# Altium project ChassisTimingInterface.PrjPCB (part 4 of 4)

## Sheet ChassisTimingInterface_SFP.SchDoc: SFP
size B; Author: M. Pirello; Organization: LIGO Laboratory; Address1: California Institute of Technology; Address2: Massachusetts Institute of Technology; Address3: National Science Foundation; Address4: Australia 2086; DocumentNumber: 3; SheetNumber: 9; SheetTotal: 12; Size: B
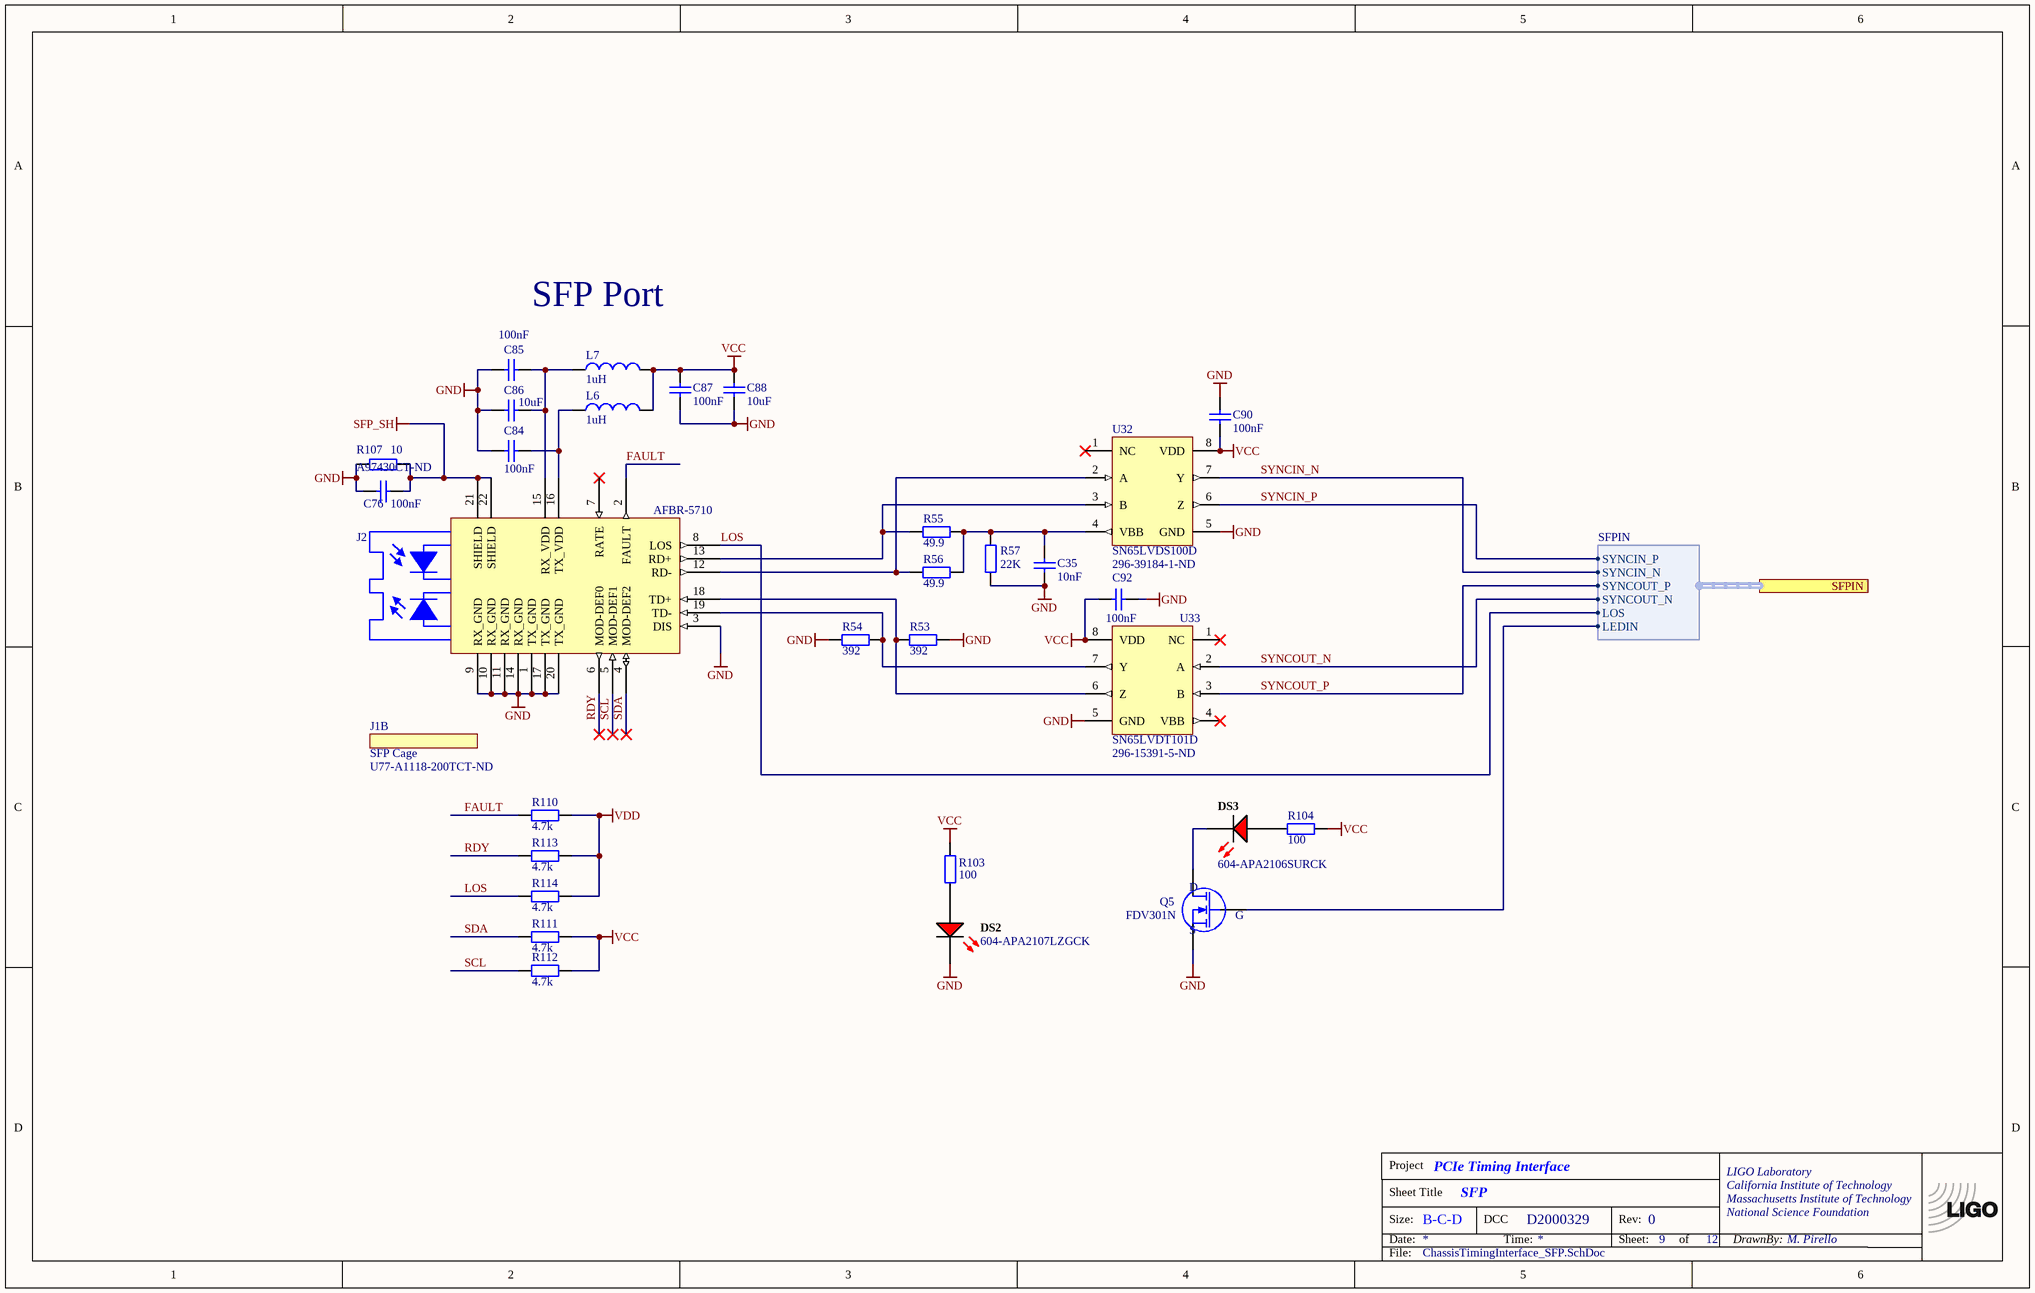
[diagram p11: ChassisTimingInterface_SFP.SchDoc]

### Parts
(Parts that share a designator on the sheet are numbered #1, #2 ... from top to bottom, then left to right.)
*#3  TitleBlock  (value not drawn)  (graphical)
C35  10nF  [CC1005-0402]
C76  100nF  [CC1005-0402]
C84  100nF  [CC1005-0402]
C85  100nF  [CC1005-0402]
C86  10uF  [CC2013-0805]
C87  100nF  [CC1005-0402]
C88  10uF  [CC2013-0805]
C90  100nF  [CC1005-0402]
C92  100nF  [CC1005-0402]
DS2  604-APA2107LZGCK  [KING-LED2107-13-RED-2_V]
DS3  604-APA2106SURCK  [KING-LED2107-13-RED-2_V]
J1B  SFP Cage  Supplier Part Number 1: U77-A1118-200TCT-ND  (mechanical)
J2  AFBR-5710  Supplier Part Number 1: A97430CT-ND  [MSA/SFP2x10]
L6  1uH  [CL2520-1008]
L7  1uH  [CL2520-1008]
Q5  FDV301N  [SO-G3/C2.25]
R53  392  [CR2012-0805]
R54  392  [CR2012-0805]
R55  49.9  [CR1608-0603]
R56  49.9  [CR1608-0603]
R57  22K  [CR2012-0805]
R103  100  [CR1608-0603]
R104  100  [CR1608-0603]
R107  value 10  [CR1005-0402]  (hidden comment: 10.0)
R110  4.7k  [CR1005-0402]
R111  4.7k  [CR1005-0402]
R112  4.7k  [CR1005-0402]
R113  4.7k  [CR1005-0402]
R114  4.7k  [CR1005-0402]
U32  SN65LVDS100D  Supplier Part Number 1: 296-39184-1-ND  [MSOP8]
U33  SN65LVDT101D  Supplier Part Number 1: 296-15391-5-ND  [MSOP8]

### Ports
SFPIN (harness SFPIN)

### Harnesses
SFPIN: SYNCIN_N, SYNCIN_P, SYNCOUT_N, SYNCOUT_P, LEDIN, LOS

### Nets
GND: C35.1 C76.2 C84.1 C85.1 C86.1 C87.1 C88.1 C90.1 C92.1 DS2.1(K) J2.1(TX_GND) J2.3(DIS) J2.9(RX_GND) J2.10(RX_GND) J2.11(RX_GND) J2.14(RX_GND) J2.17(TX_GND) J2.20(TX_GND) Q5.2(S) R53.2 R54.1 R57.2 R107.2 U32.5(GND) U33.5(GND)
SFP_SH: C76.1 J2.21(SHIELD) J2.22(SHIELD) R107.1
VCC: C87.2 C88.2 C90.2 C92.2 L6.2 L7.2 R103.2 R104.2 R111.2 R112.2 U32.8(VDD) U33.8(VDD)
VDD: R110.2 R113.2 R114.2
FAULT: J2.2(FAULT) R110.1
LOS: J2.8(LOS) R114.1 ; port SFPIN.LOS  [project net SFPIN.LOS]
RDY: J2.6(MOD-DEF0) R113.1
SCL: J2.5(MOD-DEF1) R112.1
SDA: J2.4(MOD-DEF2) R111.1
SFPIN.LEDIN: Q5.1(G) ; port SFPIN.LEDIN
SYNCIN_N: U32.7(Y) ; port SFPIN.SYNCIN_N  [project net SFPIN.SYNCIN_N]
SYNCIN_P: U32.6(Z) ; port SFPIN.SYNCIN_P  [project net SFPIN.SYNCIN_P]
SYNCOUT_N: U33.2(A) ; port SFPIN.SYNCOUT_N  [project net SFPIN.SYNCOUT_N]
SYNCOUT_P: U33.3(B) ; port SFPIN.SYNCOUT_P  [project net SFPIN.SYNCOUT_P]
NetC35_2: C35.2 R55.1 R56.1 R57.1 U32.4(VBB)
NetC84_2: C84.2 J2.16(TX_VDD) L6.1
NetC85_2: C85.2 C86.2 J2.15(RX_VDD) L7.1
NetDS2_2: DS2.2(A) R103.1
NetDS3_1: DS3.1(K) Q5.3(D)
NetDS3_2: DS3.2(A) R104.1
NetJ2_12: J2.12(RD-) R56.2 U32.2(A)
NetJ2_13: J2.13(RD+) R55.2 U32.3(B)
NetJ2_18: J2.18(TD+) R53.1 U33.6(Z)
NetJ2_19: J2.19(TD-) R54.2 U33.7(Y)

Not connected (* = marked no-connect by the designer): J2 7(RATE)* 23(POST) 24(POST); U32 1(NC)*; U33 1(NC)* 4(VBB)*

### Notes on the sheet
- SFP Port

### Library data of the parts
C35 = ChipCap: C0402 0.01uF; Part Number: 311-1349-1-ND; Tolerance: 10%
C76 C84 C85 C87 C90 C92 = ChipCap: C0402 0.1uF; Part Number: 1276-6720-1-ND; Tolerance: 10%
C86 C88 = ChipCap: C0805 10uF; Part Number: 1276-6454-1-ND; Tolerance: 10%
DS2 = CMP-0245-00001-1: 2.1x0.7mm Right Angle SMT LED, 1.3mm Thickness, Green
DS3 = CMP-0245-00001-1: 2.1x0.7mm Right Angle SMT LED, 1.3mm Thickness, Red
J1B = Partlist
J2 = AFBR-5710: fiber optic transceiver, 1.25GB/s, MM, LC, SFP
L6 L7 = ChipInductor: Inductor; Part Number: 994-1008LS-102XJLB
Q5 = FDV301N: FDV301N, Digital FET, N-channel, SOT23; Part Number: FDV301NCT-ND
R53 R54 = ChipRes1: R0805 392; Part Number: P20236CT-ND; Tolerance: 0.1%
R55 R56 = ChipRes1: R0603 49.9; Part Number: RR08Q49.9DCT-ND; Tolerance: 0.1%
R57 = ChipRes1: R0805 22k; Part Number: RR12P22.0KDCT-ND; Tolerance: 0.1%
R103 R104 = ChipRes1: R0603 100; Part Number: RR08P100DCT-ND; Tolerance: 0.1%
R107 = ChipRes1: R0402 10; Part Number: A127127CT-ND; Tolerance: 0.1%
R110-R114 = ChipRes1: R0402 4.7k; Part Number: RR05P4.7KDCT-ND; Tolerance: 0.1%
U32 U33 = SN65LVDS100: DIFF TRANSLATOR

## Sheet ChassisTimingInterface7.SchDoc: External Sync
size B; Author: M. Pirello; Organization: LIGO Laboratory; Address1: California Institute of Technology; Address2: Massachusetts Institute of Technology; Address3: National Science Foundation; Address4: Australia 2086; DocumentNumber: 8; SheetNumber: 8; SheetTotal: 12; Size: B
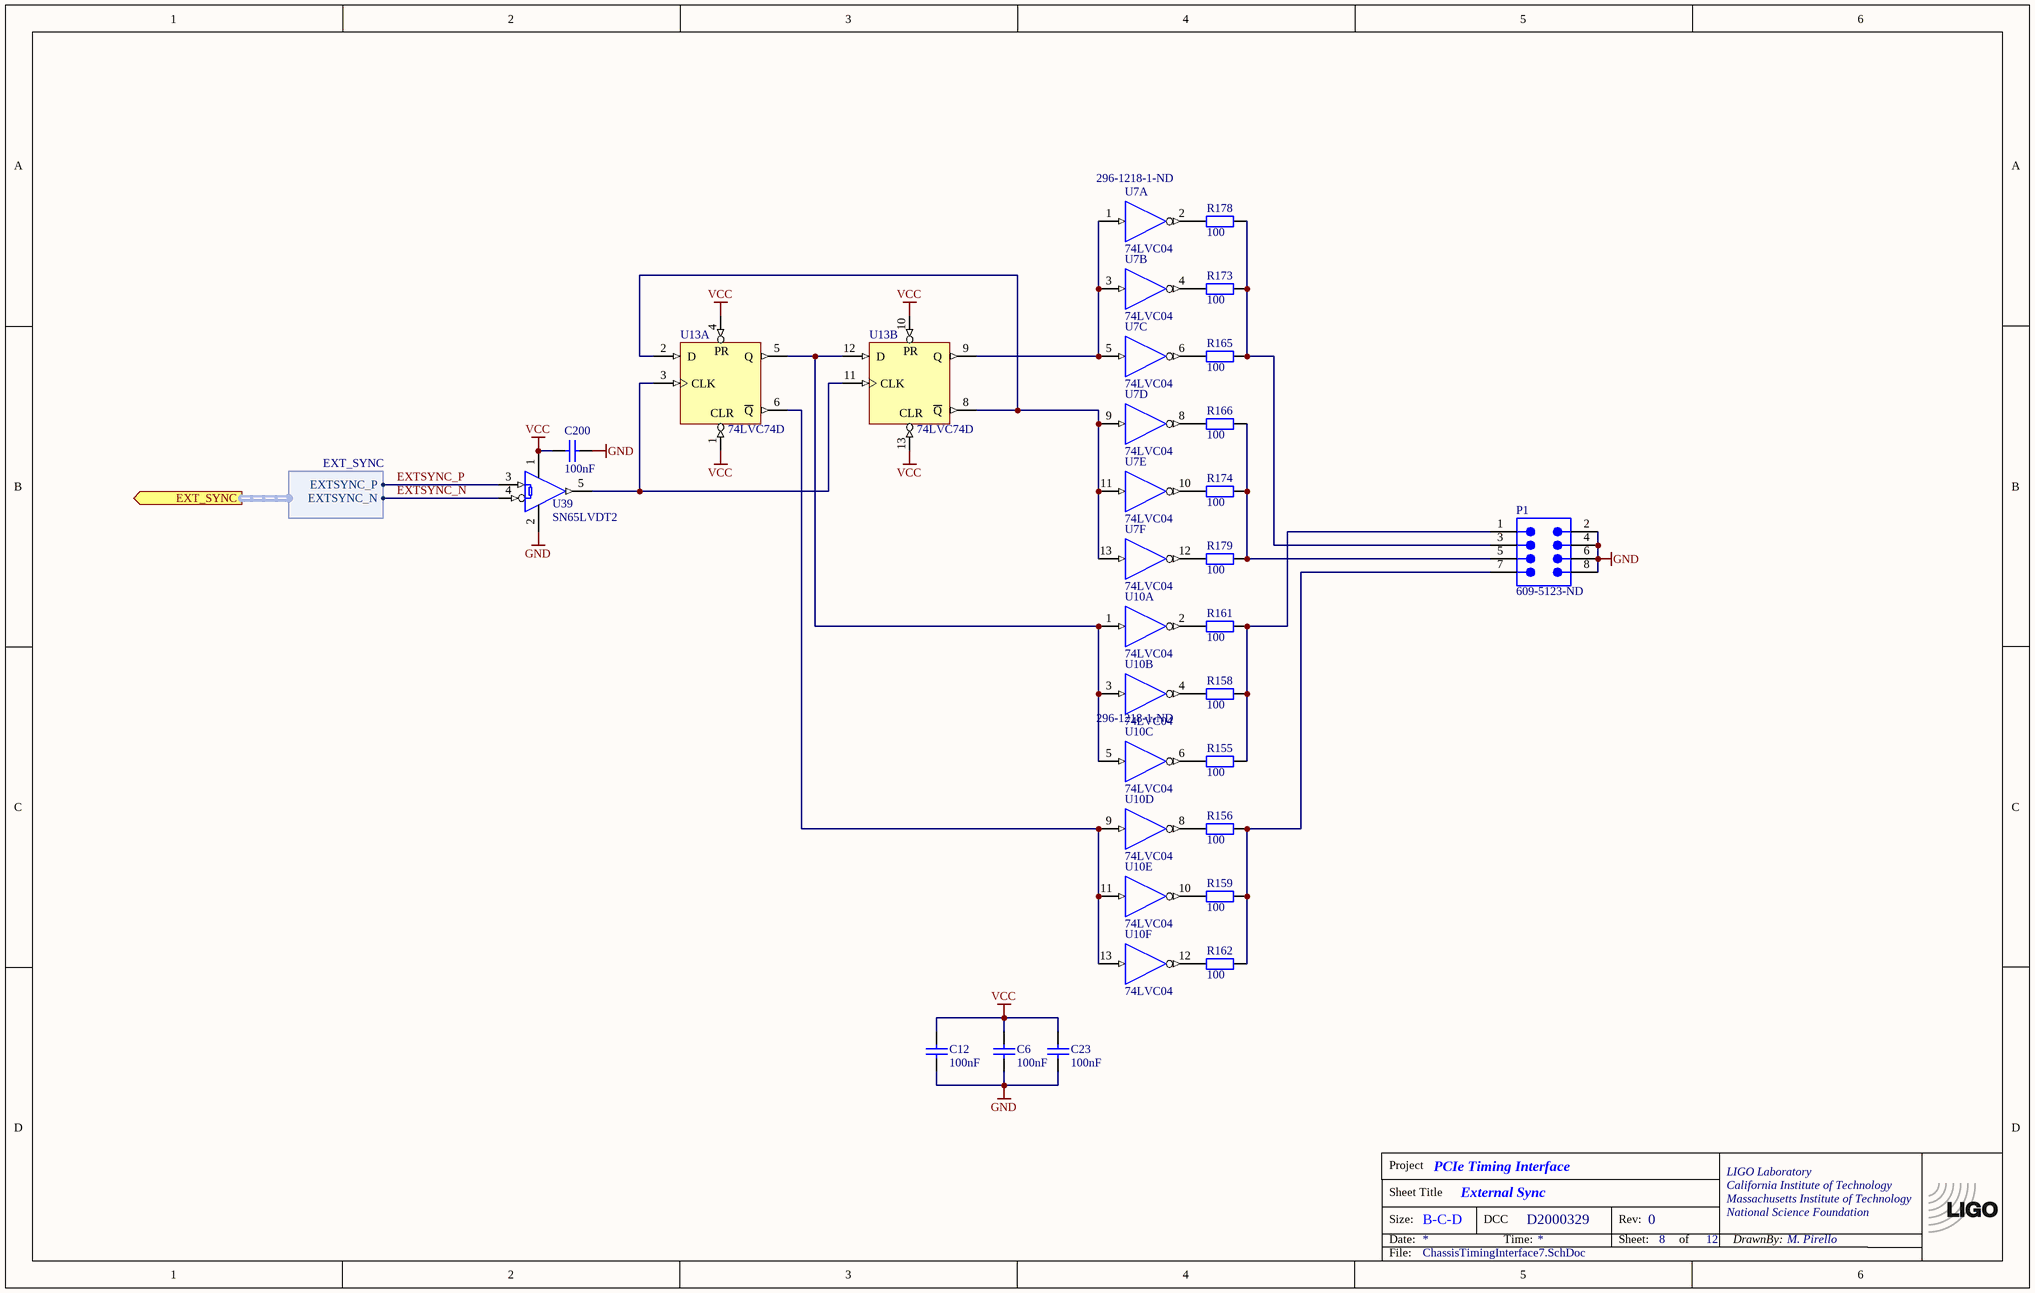
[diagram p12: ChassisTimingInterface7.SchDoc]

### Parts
(Parts that share a designator on the sheet are numbered #1, #2 ... from top to bottom, then left to right.)
*?#8  TitleBlock  (value not drawn)  (graphical)
?#2  (no value)  (no BOM)
C6  100nF  [CC1005-0402]
C12  100nF  [CC1005-0402]
C23  100nF  [CC1005-0402]
C200  100nF  [CC1005-0402]
P1  609-5123-ND  [9181089621]
R155  100  [CR1608-0603]
R156  100  [CR1608-0603]
R158  100  [CR1608-0603]
R159  100  [CR1608-0603]
R161  100  [CR1608-0603]
R162  100  [CR1608-0603]
R165  100  [CR1608-0603]
R166  100  [CR1608-0603]
R173  100  [CR1608-0603]
R174  100  [CR1608-0603]
R178  100  [CR1608-0603]
R179  100  [CR1608-0603]
U7  74LVC04  Supplier Part Number 1: 296-1218-1-ND  [TSSOP14]  (parts A,B,C,D,E,F of 6)
U10  74LVC04  [TSSOP14]  (parts A,B,C,D,E,F of 6)
U13  74LVC74D  [TSSOP14]  (parts A,B of 2)
U39  SN65LVDT2  [SO-G5/E2.4]

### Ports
EXT_SYNC (out, harness EXT_SYNC)

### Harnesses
EXT_SYNC: EXTSYNC_N, EXTSYNC_P

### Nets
GND: C6.2 C12.2 C23.2 C200.1 P1.2 P1.4 P1.6 P1.8 U7.7(GND) U10.7(GND) U13.7(GND) U39.2(GND)
VCC: C6.1 C12.1 C23.1 C200.2 U7.14(VCC) U10.14(VCC) U13.1(CLR) U13.4(PR) U13.10(PR) U13.13(CLR) U13.14(VCC) U39.1(VCC)
EXTSYNC_N: U39.4(B) ; port EXT_SYNC.EXTSYNC_N  [project net EXT_SYNC.EXTSYNC_N]
EXTSYNC_P: U39.3(A) ; port EXT_SYNC.EXTSYNC_P  [project net EXT_SYNC.EXTSYNC_P]
NetP1_1: P1.1 R155.2 R158.2 R161.2
NetP1_3: P1.3 R165.2 R173.2 R178.2
NetP1_5: P1.5 R166.2 R174.2 R179.2
NetP1_7: P1.7 R156.2 R159.2 R162.2
NetR155_1: R155.1 U10.6(Y)
NetR156_1: R156.1 U10.8(Y)
NetR158_1: R158.1 U10.4(Y)
NetR159_1: R159.1 U10.10(Y)
NetR161_1: R161.1 U10.2(Y)
NetR162_1: R162.1 U10.12(Y)
NetR165_1: R165.1 U7.6(Y)
NetR166_1: R166.1 U7.8(Y)
NetR173_1: R173.1 U7.4(Y)
NetR174_1: R174.1 U7.10(Y)
NetR178_1: R178.1 U7.2(Y)
NetR179_1: R179.1 U7.12(Y)
NetU7_1: U7.1(A) U7.3(A) U7.5(A) U13.9(Q)
NetU7_9: U7.9(A) U7.11(A) U7.13(A) U13.2(D) U13.8(~{Q})
NetU10_1: U10.1(A) U10.3(A) U10.5(A) U13.5(Q) U13.12(D)
NetU10_9: U10.9(A) U10.11(A) U10.13(A) U13.6(~{Q})
NetU13_3: U13.3(CLK) U13.11(CLK) U39.5(R)

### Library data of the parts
?#2 = LIGO_logo: LIGO logo
C6 C12 C23 C200 = ChipCap: as C76 on sheet ChassisTimingInterface_SFP
P1 = 09 18 108 9621: Flat Cable Connector (IDC), PCB Transition Connector, 2 Rows, Solder Pin, 8 Contacts
R155 R156 R158 R159 R161 R162 R165 R166 R173 R174 R178 R179 = ChipRes1: as R103 on sheet ChassisTimingInterface_SFP
U7 = SN74AHCT04D: Hex Inverter
U10 = SN74AHCT04D: Hex Inverter; Part Number: 296-1218-1-ND
U13 = 74F74PC: Dual D-Type Positive Edge-Triggered Flip-Flop; Part Number: 296-1240-5-ND
U39 = SN65LVDT2DBV: Single LVDS Receiver with 100 Ohm termination; Part Number: 296-6896-1-ND

## Sheet ChassisTimingInterface_XADC.SchDoc: XADC
size B; DocumentNumber: 5; Revision: C; SheetNumber: 10; SheetTotal: 12
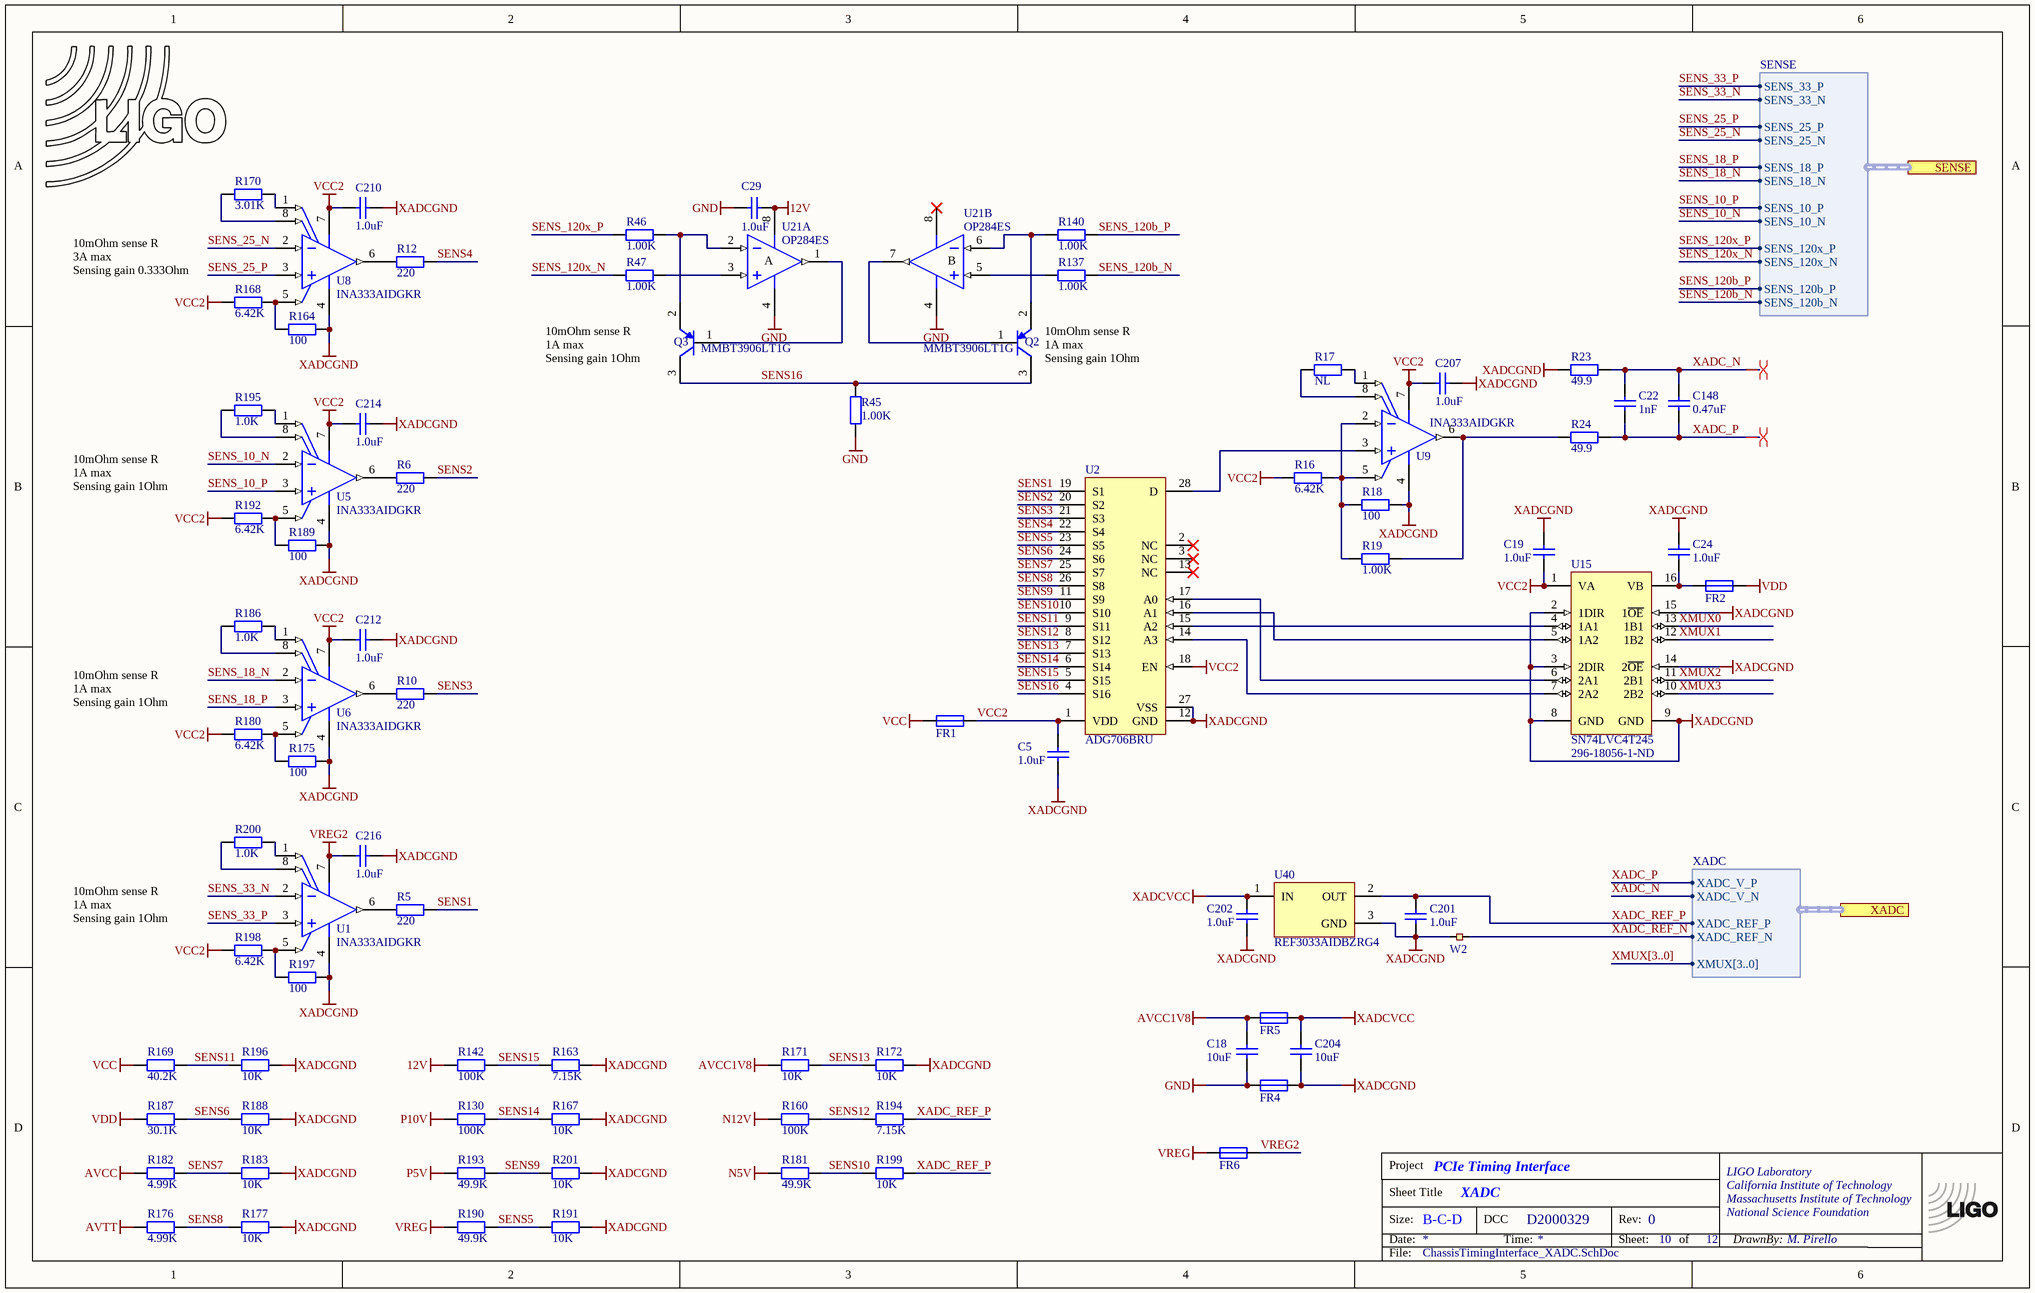
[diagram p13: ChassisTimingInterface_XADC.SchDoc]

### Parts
(Parts that share a designator on the sheet are numbered #1, #2 ... from top to bottom, then left to right.)
*#4  TitleBlock  (value not drawn)  (graphical)
C5  1.0uF  [CC1608-0603]
C18  10uF  [CC2013-0805]
C19  1.0uF  [CC1608-0603]
C22  1nF  [CC1005-0402]
C24  1.0uF  [CC1608-0603]
C29  1.0uF  [CC1608-0603]
C148  0.47uF  [CAPC0603X33X15NL03T05]
C201  1.0uF  [CC1608-0603]
C202  1.0uF  [CC1608-0603]
C204  10uF  [CC2013-0805]
C207  1.0uF  [CC1608-0603]
C210  1.0uF  [CC1608-0603]
C212  1.0uF  [CC1608-0603]
C214  1.0uF  [CC1608-0603]
C216  1.0uF  [CC1608-0603]
FR1  BLM31PG121  [CC3216-1206]  (value not drawn)
FR2  BLM31PG121  [CC3216-1206]  (value not drawn)
FR4  BLM31PG121  [CC3216-1206]  (value not drawn)
FR5  BLM31PG121  [CC3216-1206]  (value not drawn)
FR6  BLM31PG121  [CC3216-1206]  (value not drawn)
LOGO4#2  LIGO logo  [LIGO_LOGO]  (value not drawn)  (graphical)
Q2  MMBT3906LT1G  [ONSC-SOT-23-3-318-08_V]
Q3  MMBT3906LT1G  [ONSC-SOT-23-3-318-08_V]
R5  220  [CR1608-0603]
R6  220  [CR1608-0603]
R10  220  [CR1608-0603]
R12  220  [CR1608-0603]
R16  6.42K  [CR1608-0603]
R17  NL  [CR1608-0603]
R18  100  [CR1608-0603]
R19  value 1.00K  [CR1608-0603]  (hidden comment: 1.0k)
R23  49.9  [CR1608-0603]
R24  49.9  [CR1608-0603]
R45  value 1.00K  [CR1608-0603]  (hidden comment: 1.0k)
R46  value 1.00K  [CR1608-0603]  (hidden comment: 1.0k)
R47#2  value 1.00K  [CR1608-0603]  (hidden comment: 1.0k)
R130  100K  [CR1005-0402]
R137  value 1.00K  [CR1608-0603]  (hidden comment: 1.0k)
R140  value 1.00K  [CR1608-0603]  (hidden comment: 1.0k)
R142  100K  [CR1005-0402]
R160  100K  [CR1005-0402]
R163  7.15K  [CR1005-0402]
R164  100  [CR1608-0603]
R167  10K  [CR1005-0402]
R168  6.42K  [CR1608-0603]
R169  40.2K  [CR1608-0603]
R170  3.01K  [CR1608-0603]
R171  10K  [CR1005-0402]
R172  10K  [CR1005-0402]
R175  100  [CR1608-0603]
R176  4.99K  [CR1608-0603]
R177  10K  [CR1005-0402]
R180  6.42K  [CR1608-0603]
R181  49.9K  [CR1005-0402]
R182  4.99K  [CR1608-0603]
R183  10K  [CR1005-0402]
R186  1.0K  [CR1608-0603]
R187  30.1K  [CR1608-0603]
R188  10K  [CR1005-0402]
R189  100  [CR1608-0603]
R190  49.9K  [CR1005-0402]
R191  10K  [CR1005-0402]
R192  6.42K  [CR1608-0603]
R193  49.9K  [CR1005-0402]
R194  7.15K  [CR1005-0402]
R195  1.0K  [CR1608-0603]
R196  10K  [CR1005-0402]
R197  100  [CR1608-0603]
R198  6.42K  [CR1608-0603]
R199  10K  [CR1005-0402]
R200  1.0K  [CR1608-0603]
R201  10K  [CR1005-0402]
U1  INA333AIDGKR  [DGK0008A_N]
U2  ADG706BRU  [ADI-RU-28_M]
U5  INA333AIDGKR  [DGK0008A_N]
U6  INA333AIDGKR  [DGK0008A_N]
U8  INA333AIDGKR  [DGK0008A_N]
U9  INA333AIDGKR  [DGK0008A_N]
U15  SN74LVC4T245  Supplier Part Number 1: 296-18056-1-ND  [TSSOP16]
U21  OP284ES  [SO-8_N]  (parts A,B of 2)
U40  REF3033AIDBZRG4  [TI-DBZ3_N]
W2  Net tie  [NETTIE1_SMDTOP]  (value not drawn)  (net tie, no BOM)

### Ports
SENSE (harness SENSE), XADC (harness XADC)

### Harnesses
XADC: XADC_REF_P, XADC_V_N, XADC_V_P, XMUX[3..0], XADC_REF_N
SENSE: SENS_33_P, SENS_33_N, SENS_25_P, SENS_25_N, SENS_18_P, SENS_18_N, SENS_10_P, SENS_10_N, SENS_120x_P, SENS_120x_N, SENS_120b_P, SENS_120b_N

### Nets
12V: C29.1 R47#2.2 R137.1 R142.1 U21.8(V+) ; port SENSE.SENS_120x_N, port SENSE.SENS_120b_N  [also labelled SENS_120b_N, SENS_120x_N]
AVCC: R182.1
AVCC1V8: C18.1 FR5.1 R171.1
AVTT: R176.1
GND: C18.2 C29.2 FR4.1 R45.2 U21.4(V-)
N5V: R181.1
N12V: R160.1
P5V: R193.1
P10V: R130.1
SENS_10_N: U5.2(VIN-) ; port SENSE.SENS_10_N  [project net VCCINT]
SENS_18_N: U6.2(VIN-) ; port SENSE.SENS_18_N  [project net VCC1V8]
VCC: FR1.1 R169.1 U1.2(VIN-) ; port SENSE.SENS_33_N  [also labelled SENS_33_N]
VCC2: C5.1 C19.2 C207.1 C210.1 C212.1 C214.1 FR1.2 R16.1 R168.1 R180.1 R192.1 R198.1 U2.1(VDD) U2.18(EN) U5.7(V+) U6.7(V+) U8.7(V+) U9.7(V+) U15.1(VA)
VDD: FR2.2 R187.1 U8.2(VIN-) ; port SENSE.SENS_25_N  [also labelled SENS_25_N]
VREG: FR6.1 R190.1
VREG2: C216.1 FR6.2 U1.7(V+)
XADCGND: C5.2 C19.1 C24.1 C201.2 C202.2 C204.2 C207.2 C210.2 C212.2 C214.2 C216.2 FR4.2 R18.2 R23.1 R163.2 R164.2 R167.2 R172.2 R175.2 R177.2 R183.2 R188.2 R189.2 R191.2 R196.2 R197.2 R201.2 U1.4(V-) U2.12(GND) U2.27(VSS) U5.4(V-) U6.4(V-) U8.4(V-) U9.4(V-) U15.2(1DIR) U15.3(2DIR) U15.8(GND) U15.9(GND) U15.14(2~{OE}) U15.15(1~{OE}) U40.3(GND) W2.1
XADCVCC: C202.1 C204.1 FR5.2 U40.1(IN)
SENS1: R5.2 U2.19(S1)
SENS2: R6.2 U2.20(S2)
SENS3: R10.2 U2.21(S3)
SENS4: R12.2 U2.22(S4)
SENS5: R190.2 R191.1 U2.23(S5)
SENS6: R187.2 R188.1 U2.24(S6)
SENS7: R182.2 R183.1 U2.25(S7)
SENS8: R176.2 R177.1 U2.26(S8)
SENS9: R193.2 R201.1 U2.11(S9)
SENS10: R181.2 R199.1 U2.10(S10)
SENS11: R169.2 R196.1 U2.9(S11)
SENS12: R160.2 R194.1 U2.8(S12)
SENS13: R171.2 R172.1 U2.7(S13)
SENS14: R130.2 R167.1 U2.6(S14)
SENS15: R142.2 R163.1 U2.5(S15)
SENS16: Q2.3(C) Q3.3(C) R45.1 U2.4(S16)
SENS_10_P: U5.3(VIN+) ; port SENSE.SENS_10_P  [project net SENSE.SENS_10_P]
SENS_18_P: U6.3(VIN+) ; port SENSE.SENS_18_P  [project net SENSE.SENS_18_P]
SENS_25_P: U8.3(VIN+) ; port SENSE.SENS_25_P  [project net SENSE.SENS_25_P]
SENS_33_P: U1.3(VIN+) ; port SENSE.SENS_33_P  [project net SENSE.SENS_33_P]
SENS_120b_P: R140.1 ; port SENSE.SENS_120b_P  [project net SENSE.SENS_120b_P]
SENS_120x_P: R46.2 ; port SENSE.SENS_120x_P  [project net SENSE.SENS_120x_P]
XADC_N: C22.2 C148.2 R23.2 ; port XADC.XADC_V_N  [project net XADC.XADC_V_N]
XADC_P: C22.1 C148.1 R24.2 ; port XADC.XADC_V_P  [project net XADC.XADC_V_P]
XADC_REF_N: W2.2 ; port XADC.XADC_REF_N  [project net XADC.XADC_REF_N]
XADC_REF_P: C201.1 R194.2 R199.2 U40.2(OUT) ; port XADC.XADC_REF_P  [project net XADC.XADC_REF_P]
XMUX0: U15.13(1B1)
XMUX1: U15.12(1B2)
XMUX2: U15.11(2B1)
XMUX3: U15.10(2B2)
NetC24_2: C24.2 FR2.1 U15.16(VB)
NetQ2_1: Q2.1(B) U21.7(OUT)
NetQ2_2: Q2.2(E) R140.2 U21.6(IN-)
NetQ3_1: Q3.1(B) U21.1(OUT)
NetQ3_2: Q3.2(E) R46.1 U21.2(IN-)
NetR5_1: R5.1 U1.6(VOUT)
NetR6_1: R6.1 U5.6(VOUT)
NetR10_1: R10.1 U6.6(VOUT)
NetR12_1: R12.1 U8.6(VOUT)
NetR16_2: R16.2 R18.1 R19.1 U9.2(VIN-) U9.5(REF)
NetR17_1: R17.1 U9.8(RG)
NetR17_2: R17.2 U9.1(RG)
NetR19_2: R19.2 R24.1 U9.6(VOUT)
NetR47#2_1: R47#2.1 U21.3(IN+)
NetR137_2: R137.2 U21.5(IN+)
NetR164_1: R164.1 R168.2 U8.5(REF)
NetR170_1: R170.1 U8.8(RG)
NetR170_2: R170.2 U8.1(RG)
NetR175_1: R175.1 R180.2 U6.5(REF)
NetR186_1: R186.1 U6.8(RG)
NetR186_2: R186.2 U6.1(RG)
NetR189_1: R189.1 R192.2 U5.5(REF)
NetR195_1: R195.1 U5.8(RG)
NetR195_2: R195.2 U5.1(RG)
NetR197_1: R197.1 R198.2 U1.5(REF)
NetR200_1: R200.1 U1.8(RG)
NetR200_2: R200.2 U1.1(RG)
NetU2_14: U2.14(A3) U15.7(2A2)
NetU2_15: U2.15(A2) U15.4(1A1)
NetU2_16: U2.16(A1) U15.5(1A2)
NetU2_17: U2.17(A0) U15.6(2A1)
NetU2_28: U2.28(D) U9.3(VIN+)

Not connected (* = marked no-connect by the designer): U2 2(NC)* 3(NC)* 13(NC)*

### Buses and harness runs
bus XMUX[3..0]

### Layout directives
differential pair: XADC.XADC_V_N, XADC.XADC_V_P

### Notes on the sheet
- 10mOhm sense R
  3A max
  Sensing gain 0.333Ohm
- (near Q3) 10mOhm sense R
  1A max
  Sensing gain 1Ohm
- (near Q2) 10mOhm sense R
  1A max
  Sensing gain 1Ohm
- 10mOhm sense R
  1A max
  Sensing gain 1Ohm

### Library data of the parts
C5 C19 C24 C29 C201 C202 C207 C210 C212 C214 C216 = ChipCap: C0603 1.0uF; Part Number: 1276-1184-1-ND; Tolerance: 10%
C18 C204 = ChipCap: as C86 on sheet ChassisTimingInterface_SFP
C22 = ChipCap: C0402 1.0nF; Part Number: 1292-1246-1-ND; Tolerance: 10%
C148 = CMP-2010-00306-1: C0201 0.47uF; Part Number: 1276-6445-1-ND; Tolerance: 10%
FR1 FR2 FR4-FR6 = BLM31PG121SN1: ferrite bead, 120Ohm at 100MHz, 1206; Part Number: 490-1056-1-ND
LOGO4#2 = LIGO_logo
Q2 Q3 = CMP-1048-00670-1: General Purpose Transistor, PNP Silicon, 3-Pin SOT-23, Pb-Free, Tape and Reel; Part Number: MMBT3906LT1GOSCT-ND
R5 R6 R10 R12 = ChipRes1: R0603 220; Part Number: RR08P220DCT-ND; Tolerance: 0.1%
R16 R168 R180 R192 R198 = ChipRes1: R0603 6.42k; Part Number: RR08P6.49KDCT-ND; Tolerance: 0.1%
R17 = ChipRes1: Resistor, surface mount; Tolerance: 0.1%
R18 R164 R175 R189 R197 = ChipRes1: as R103 on sheet ChassisTimingInterface_SFP
R19 R45 R46 R47#2 R137 R140 = ChipRes1: R0603 1.0k; Part Number: RR08P1.0KDCT-ND; Tolerance: 1%
R23 R24 = ChipRes1: as R55 on sheet ChassisTimingInterface_SFP
R130 R142 R160 = ChipRes1: R0402 100k; Part Number: RR05P100KDCT-ND; Tolerance: 0.1%
R163 R194 = ChipRes1: R0402 7.15k; Part Number: YAG1478CT-ND; Tolerance: 0.1%
R167 R171 R172 R177 R183 R188 R191 R196 R199 R201 = ChipRes1: R0402 10k; Part Number: RR05P10.0KDCT-ND; Tolerance: 0.1%
R169 = ChipRes1: R0603 40.2k; Part Number: RR08P40.2KDCT-ND; Tolerance: 0.1%
R170 = ChipRes1: R0603 3.01k; Part Number: RR08P3.01KDCT-ND; Tolerance: 0.1%
R176 R182 = ChipRes1: R0603 4.99k; Part Number: RR08P4.99KDCT-ND; Tolerance: 0.1%
R181 R190 R193 = ChipRes1: R0402 49.9k; Part Number: RR05P49.9KDCT-ND; Tolerance: 0.1%
R186 R195 R200 = ChipRes1: R0603 1.0k; Part Number: RR08P1.0KDCT-ND; Tolerance: 0.1%
R187 = ChipRes1: R0603 30.1k; Part Number: RR08P30.1KDCT-ND; Tolerance: 0.1%
U1 U5 U6 U8 U9 = CMP-0944-00088-2: Low Power, Precision Instrumentation Amplifier, -40 to 125 degC, 8-pin SOP (DGK8), Green (RoHS & no Sb/Br); Part Number: 296-23564-1-ND
U2 = CMP-0798-00217-1: 1.8 to 5.5 V / 2.5 V, CMOS Low-Voltage 2.5 Ohm, 16-Channel Multiplexer, -40 to 85 degC, 28-pin SOP (RU-28), Tube; Part Number: ADG706BRUZ-REEL7CT-ND
U15 = SN74LVC4T245: Quad-Bit Dual Supply Transceiver
U21 = OP284ES: Precision Rail-to-Rail Input and Output Operational Amplifier; Part Number: OP284ESZ-REEL7TR-ND
U40 = CMP-0367-00169-1: 3.3 V, 50 ppm / degC, 50 uA Series (Bandgap) Voltage Reference, -40 to 125 degC, 3-pin SOT-23 (DBZ), Green (RoHS & no Sb/Br); Part Number: 296-52689-1-ND
W2 = NetTie1_small: Tie two nets together

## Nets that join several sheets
12V: ChassisTimingInterface1 (P5.77 P5.79), ChassisTimingInterface2 (FL5.1), ChassisTimingInterface4 (13 pins), ChassisTimingInterfacePCIE_HL (R143.2), ChassisTimingInterface6 (5 pins), ChassisTimingInterface_XADC (5 pins)
AVCC: FPGA_ARTIX7 (5 pins), ChassisTimingInterfacePCIE_HL (10 pins), ChassisTimingInterface_XADC (R182.1)
AVCC1V8: ChassisTimingInterface4 (C37.2 R58.2 TP9.1 U26.7), ChassisTimingInterface_XADC (C18.1 FR5.1 R171.1)
AVTT: FPGA_ARTIX7 (7 pins), ChassisTimingInterfacePCIE_HL (10 pins), ChassisTimingInterface_XADC (R176.1)
BUS12V: ChassisTimingInterfacePCIE_HL (FL1.1), ChassisTimingInterfacePCIE (5 pins)
GND: ChassisTimingInterface1 (38 pins), ChassisTimingInterface2 (15 pins), ChassisTimingInterface4 (61 pins), ChassisTimingInterface3 (21 pins), ChassisTimingInterface5 (73 pins), FPGA_ARTIX7 (94 pins), ChassisTimingInterfacePCIE_HL (37 pins), ChassisTimingInterfacePCIE (9 pins), ChassisTimingInterface6 (20 pins), ChassisTimingInterface_SFP (25 pins), ChassisTimingInterface7 (12 pins), ChassisTimingInterface_XADC (5 pins)
N5V: ChassisTimingInterface6 (8 pins), ChassisTimingInterface_XADC (R181.1)
N12V: ChassisTimingInterface6 (6 pins), ChassisTimingInterface_XADC (R160.1)
P5V: ChassisTimingInterface6 (17 pins), ChassisTimingInterface_XADC (R193.1)
P10V: ChassisTimingInterface2 (10 pins), ChassisTimingInterface_XADC (R130.1)
VCC: ChassisTimingInterface1 (P5.1 P5.3 P5.5 P5.7), ChassisTimingInterface2 (15 pins), ChassisTimingInterface4 (R49.2 R108.2 R109.2 TP12.1), ChassisTimingInterface6 (8 pins), ChassisTimingInterface_SFP (12 pins), ChassisTimingInterface7 (12 pins), ChassisTimingInterface_XADC (FR1.1 R169.1 U1.2)
VCC1V8: ChassisTimingInterface4 (R48.2 R124.2 TP10.1), ChassisTimingInterface5 (9 pins), FPGA_ARTIX7 (5 pins), ChassisTimingInterfacePCIE_HL (L1.2 L8.2), ChassisTimingInterface_XADC (U6.2)
VCCINT: ChassisTimingInterface4 (R96.2 R126.2 TP22.1), ChassisTimingInterface5 (23 pins), FPGA_ARTIX7 (17 pins), ChassisTimingInterface_XADC (U5.2)
VDD: ChassisTimingInterface1 (P4.74 P4.76 P5.73 P5.75), ChassisTimingInterface2 (U22.10), ChassisTimingInterface4 (9 pins), ChassisTimingInterface3 (21 pins), ChassisTimingInterface5 (41 pins), FPGA_ARTIX7 (37 pins), ChassisTimingInterfacePCIE_HL (C196.1 U38.1), ChassisTimingInterface_SFP (R110.2 R113.2 R114.2), ChassisTimingInterface_XADC (FR2.2 R187.1 U8.2)
VREG: ChassisTimingInterface4 (7 pins), ChassisTimingInterface_XADC (FR6.1 R190.1)
XADCGND: ChassisTimingInterface5 (C154.1), FPGA_ARTIX7 (U16.K9), ChassisTimingInterface_XADC (42 pins)
XADCVCC: ChassisTimingInterface5 (C154.2), FPGA_ARTIX7 (U16.K10), ChassisTimingInterface_XADC (C202.1 C204.1 FR5.2 U40.1)
+3.3V: ChassisTimingInterfacePCIE_HL (C195.1 R148.2 U38.6), ChassisTimingInterfacePCIE (P3.A9 P3.A10 P3.B8)
BACKPLANE.CLK0_N: ChassisTimingInterface1 (J1.21), FPGA_ARTIX7 (U16.C20)
BACKPLANE.CLK0_P: ChassisTimingInterface1 (J1.2), FPGA_ARTIX7 (U16.D20)
BACKPLANE.CLK1_N: ChassisTimingInterface1 (J1.30), FPGA_ARTIX7 (U16.B16)
BACKPLANE.CLK1_P: ChassisTimingInterface1 (J1.11), FPGA_ARTIX7 (U16.B15)
BACKPLANE.CLK2_N: ChassisTimingInterface1 (J1.29), FPGA_ARTIX7 (U16.C15)
BACKPLANE.CLK2_P: ChassisTimingInterface1 (J1.10), FPGA_ARTIX7 (U16.C14)
BACKPLANE.CLK3_N: ChassisTimingInterface1 (J1.28), FPGA_ARTIX7 (U16.A19)
BACKPLANE.CLK3_P: ChassisTimingInterface1 (J1.9), FPGA_ARTIX7 (U16.A18)
BACKPLANE.CLK4_N: ChassisTimingInterface1 (J1.27), FPGA_ARTIX7 (U16.D15)
BACKPLANE.CLK4_P: ChassisTimingInterface1 (J1.8), FPGA_ARTIX7 (U16.D14)
BACKPLANE.CLK5_N: ChassisTimingInterface1 (J1.26), FPGA_ARTIX7 (U16.A20)
BACKPLANE.CLK5_P: ChassisTimingInterface1 (J1.7), FPGA_ARTIX7 (U16.B20)
BACKPLANE.CLK6_N: ChassisTimingInterface1 (J1.25), FPGA_ARTIX7 (U16.D16)
BACKPLANE.CLK6_P: ChassisTimingInterface1 (J1.6), FPGA_ARTIX7 (U16.E16)
BACKPLANE.CLK7_N: ChassisTimingInterface1 (J1.24), FPGA_ARTIX7 (U16.A21)
BACKPLANE.CLK7_P: ChassisTimingInterface1 (J1.5), FPGA_ARTIX7 (U16.B21)
BACKPLANE.CLK8_N: ChassisTimingInterface1 (J1.23), FPGA_ARTIX7 (U16.C19)
BACKPLANE.CLK8_P: ChassisTimingInterface1 (J1.4), FPGA_ARTIX7 (U16.C18)
BACKPLANE.CLK9_N: ChassisTimingInterface1 (J1.22), FPGA_ARTIX7 (U16.B22)
BACKPLANE.CLK9_P: ChassisTimingInterface1 (J1.3), FPGA_ARTIX7 (U16.C22)
BACKPLANE.CS_N: ChassisTimingInterface1 (J1.32), FPGA_ARTIX7 (U16.B13)
BACKPLANE.CS_P: ChassisTimingInterface1 (J1.13), FPGA_ARTIX7 (U16.C13)
BACKPLANE.DIN_N: ChassisTimingInterface1 (J1.35), FPGA_ARTIX7 (U16.A14)
BACKPLANE.DIN_P: ChassisTimingInterface1 (J1.16), FPGA_ARTIX7 (U16.A13)
BACKPLANE.DOUT_N: ChassisTimingInterface1 (J1.34), FPGA_ARTIX7 (U16.G13)
BACKPLANE.DOUT_P: ChassisTimingInterface1 (J1.15), FPGA_ARTIX7 (U16.H13)
BACKPLANE.SCLK_N: ChassisTimingInterface1 (J1.33), FPGA_ARTIX7 (U16.A16)
BACKPLANE.SCLK_P: ChassisTimingInterface1 (J1.14), FPGA_ARTIX7 (U16.A15)
BACKPLANE.X1_N: ChassisTimingInterface1 (R203.1), FPGA_ARTIX7 (U16.E14)
BACKPLANE.X1_P: ChassisTimingInterface1 (R202.1), FPGA_ARTIX7 (U16.E13)
BACKPLANE.X3_N: ChassisTimingInterface1 (J1.31), FPGA_ARTIX7 (U16.B18)
BACKPLANE.X3_P: ChassisTimingInterface1 (J1.12), FPGA_ARTIX7 (U16.B17)
BACKPLANE.X5_N: ChassisTimingInterface1 (J1.20), FPGA_ARTIX7 (U16.D21)
BACKPLANE.X5_P: ChassisTimingInterface1 (J1.1), FPGA_ARTIX7 (U16.E21)
CFG_CLK: ChassisTimingInterface1 (P4.79), FPGA_ARTIX7 (U16.AA3)
CFG_CS: ChassisTimingInterface1 (P4.80), FPGA_ARTIX7 (U16.AB1)
CFG_SI: ChassisTimingInterface1 (P4.77), FPGA_ARTIX7 (U16.Y3)
CFG_SO: ChassisTimingInterface1 (P4.78), FPGA_ARTIX7 (U16.AA1)
CLOCK.ACLK_N: ChassisTimingInterface2 (U17.6), FPGA_ARTIX7 (U16.AB22)
CLOCK.ACLK_P: ChassisTimingInterface2 (U17.5), FPGA_ARTIX7 (U16.AB21)
CLOCK.ACNV_N: ChassisTimingInterface2 (U17.8), FPGA_ARTIX7 (U16.AA21)
CLOCK.ACNV_P: ChassisTimingInterface2 (U17.7), FPGA_ARTIX7 (U16.AA20)
CLOCK.AIN_N: ChassisTimingInterface2 (U17.10), FPGA_ARTIX7 (U16.Y22)
CLOCK.AIN_P: ChassisTimingInterface2 (U17.9), FPGA_ARTIX7 (U16.Y21)
CLOCK.CNTROUT_N: ChassisTimingInterface2 (U17.4), FPGA_ARTIX7 (U16.AB20)
CLOCK.CNTROUT_P: ChassisTimingInterface2 (U17.3), FPGA_ARTIX7 (U16.AA19)
CLOCK.OSCCLK_N: ChassisTimingInterface2 (U27.4), FPGA_ARTIX7 (U16.Y19)
CLOCK.OSCCLK_P: ChassisTimingInterface2 (U27.5), FPGA_ARTIX7 (U16.Y18)
CLOCK.SYNC_N: ChassisTimingInterface2 (U17.2), FPGA_ARTIX7 (U16.AB18)
CLOCK.SYNC_P: ChassisTimingInterface2 (U17.1), FPGA_ARTIX7 (U16.AA18)
DAC_REF.DOUT0_N: FPGA_ARTIX7 (U16.B2), ChassisTimingInterface6 (U14.6)
DAC_REF.DOUT0_P: FPGA_ARTIX7 (U16.C2), ChassisTimingInterface6 (U14.5)
DAC_REF.DOUT1_N: FPGA_ARTIX7 (U16.A1), ChassisTimingInterface6 (U14.8)
DAC_REF.DOUT1_P: FPGA_ARTIX7 (U16.B1), ChassisTimingInterface6 (U14.7)
DAC_REF.DSCLK_N: FPGA_ARTIX7 (U16.D1), ChassisTimingInterface6 (U14.2)
DAC_REF.DSCLK_P: FPGA_ARTIX7 (U16.E1), ChassisTimingInterface6 (U14.1)
DAC_REF.DSYNC_N: FPGA_ARTIX7 (U16.D2), ChassisTimingInterface6 (U14.4)
DAC_REF.DSYNC_P: FPGA_ARTIX7 (U16.E2), ChassisTimingInterface6 (U14.3)
DAC_REF.INVSYNC_N: FPGA_ARTIX7 (U16.W5), ChassisTimingInterface6 (U35.4)
DAC_REF.INVSYNC_P: FPGA_ARTIX7 (U16.W6), ChassisTimingInterface6 (U35.3)
DAC_REF.REFCLK_N: FPGA_ARTIX7 (U16.W20), ChassisTimingInterface6 (U29.6)
DAC_REF.REFCLK_P: FPGA_ARTIX7 (U16.W19), ChassisTimingInterface6 (U29.7)
DUOTONE_N: ChassisTimingInterface1 (J1.36), ChassisTimingInterface6 (R1.2)
DUOTONE_P: ChassisTimingInterface1 (J1.17), ChassisTimingInterface6 (R2.2)
EXT_SYNC.EXTSYNC_N: FPGA_ARTIX7 (U16.L13), ChassisTimingInterface7 (U39.4)
EXT_SYNC.EXTSYNC_P: FPGA_ARTIX7 (U16.M13), ChassisTimingInterface7 (U39.3)
PCIE.PCIE_CLK_N: FPGA_ARTIX7 (U16.E6), ChassisTimingInterfacePCIE_HL (C198.2)
PCIE.PCIE_CLK_P: FPGA_ARTIX7 (U16.F6), ChassisTimingInterfacePCIE_HL (C199.2)
PCIE.PCIE_PERST: FPGA_ARTIX7 (U16.F4), ChassisTimingInterfacePCIE_HL (U38.3)
PCIE.PCIE_PWRGD: FPGA_ARTIX7 (U16.T3), ChassisTimingInterfacePCIE_HL (R149.1 U37.5)
PCIE.PCIE_RX0_N: FPGA_ARTIX7 (U16.A8), ChassisTimingInterfacePCIE (P3.B14)
PCIE.PCIE_RX0_P: FPGA_ARTIX7 (U16.B8), ChassisTimingInterfacePCIE (P3.B15)
PCIE.PCIE_TX0_N: FPGA_ARTIX7 (U16.A4), ChassisTimingInterfacePCIE_HL (C194.2)
PCIE.PCIE_TX0_P: FPGA_ARTIX7 (U16.B4), ChassisTimingInterfacePCIE_HL (C193.2)
PER0_N: ChassisTimingInterfacePCIE_HL (C193.1), ChassisTimingInterfacePCIE (P3.A17)
PER0_P: ChassisTimingInterfacePCIE_HL (C194.1), ChassisTimingInterfacePCIE (P3.A16)
PERST#: ChassisTimingInterfacePCIE_HL (R146.1), ChassisTimingInterfacePCIE (P3.A11)
POWER.PWRGOOD: ChassisTimingInterface4 (R72.1 U26.20), FPGA_ARTIX7 (U16.AB5)
POWER.PWRINT: ChassisTimingInterface4 (R63.1), FPGA_ARTIX7 (U16.AA5)
POWER.PWRSCL: ChassisTimingInterface4 (R85.1), FPGA_ARTIX7 (U16.AA6)
POWER.PWRSDA: ChassisTimingInterface4 (R84.1), FPGA_ARTIX7 (U16.Y6)
POWER.PWRSYNC_N: ChassisTimingInterface4 (U30.4), FPGA_ARTIX7 (U16.AB2)
POWER.PWRSYNC_P: ChassisTimingInterface4 (U30.3), FPGA_ARTIX7 (U16.AB3)
PRSNT1#: ChassisTimingInterfacePCIE_HL (R154.2), ChassisTimingInterfacePCIE (P3.A1)
PRSNT2#: ChassisTimingInterfacePCIE_HL (R154.1), ChassisTimingInterfacePCIE (P3.B17)
REFCLK_N: ChassisTimingInterfacePCIE_HL (C198.1), ChassisTimingInterfacePCIE (P3.A14)
REFCLK_P: ChassisTimingInterfacePCIE_HL (C199.1), ChassisTimingInterfacePCIE (P3.A13)
S1_16.S1_N: ChassisTimingInterface1 (P4.12), FPGA_ARTIX7 (U16.G4)
S1_16.S1_P: ChassisTimingInterface1 (P4.10), FPGA_ARTIX7 (U16.H4)
S1_16.S2_N: ChassisTimingInterface1 (P4.14), FPGA_ARTIX7 (U16.F1)
S1_16.S2_P: ChassisTimingInterface1 (P4.16), FPGA_ARTIX7 (U16.G1)
S1_16.S3_N: ChassisTimingInterface1 (P4.20), FPGA_ARTIX7 (U16.J6)
S1_16.S3_P: ChassisTimingInterface1 (P4.18), FPGA_ARTIX7 (U16.K6)
S1_16.S4_N: ChassisTimingInterface1 (P4.22), FPGA_ARTIX7 (U16.J1)
S1_16.S4_P: ChassisTimingInterface1 (P4.24), FPGA_ARTIX7 (U16.K1)
S1_16.S5_N: ChassisTimingInterface1 (P4.28), FPGA_ARTIX7 (U16.M5)
S1_16.S5_P: ChassisTimingInterface1 (P4.26), FPGA_ARTIX7 (U16.M6)
S1_16.S6_N: ChassisTimingInterface1 (P4.30), FPGA_ARTIX7 (U16.L1)
S1_16.S6_P: ChassisTimingInterface1 (P4.32), FPGA_ARTIX7 (U16.M1)
S1_16.S7_N: ChassisTimingInterface1 (P4.36), FPGA_ARTIX7 (U16.R2)
S1_16.S7_P: ChassisTimingInterface1 (P4.34), FPGA_ARTIX7 (U16.R3)
S1_16.S8_N: ChassisTimingInterface1 (P4.38), FPGA_ARTIX7 (U16.J4)
S1_16.S8_P: ChassisTimingInterface1 (P4.40), FPGA_ARTIX7 (U16.K4)
S1_16.S9_N: ChassisTimingInterface1 (P4.44), FPGA_ARTIX7 (U16.T4)
S1_16.S9_P: ChassisTimingInterface1 (P4.42), FPGA_ARTIX7 (U16.R4)
S10_N: ChassisTimingInterface1 (P4.46), FPGA_ARTIX7 (U16.P1)
S10_P: ChassisTimingInterface1 (P4.48), FPGA_ARTIX7 (U16.R1)
S11_N: ChassisTimingInterface1 (P4.52), FPGA_ARTIX7 (U16.U1)
S11_P: ChassisTimingInterface1 (P4.50), FPGA_ARTIX7 (U16.T1)
S12_N: ChassisTimingInterface1 (P4.54), FPGA_ARTIX7 (U16.N5)
S12_P: ChassisTimingInterface1 (P4.56), FPGA_ARTIX7 (U16.P6)
S13_N: ChassisTimingInterface1 (P4.60), FPGA_ARTIX7 (U16.V2)
S13_P: ChassisTimingInterface1 (P4.58), FPGA_ARTIX7 (U16.U2)
S14_N: ChassisTimingInterface1 (P4.62), FPGA_ARTIX7 (U16.H15)
S14_P: ChassisTimingInterface1 (P4.64), FPGA_ARTIX7 (U16.J15)
S15_N: ChassisTimingInterface1 (P4.68), FPGA_ARTIX7 (U16.Y1)
S15_P: ChassisTimingInterface1 (P4.66), FPGA_ARTIX7 (U16.W1)
S16_N: ChassisTimingInterface1 (P4.70), FPGA_ARTIX7 (U16.W4)
S16_P: ChassisTimingInterface1 (P4.72), FPGA_ARTIX7 (U16.V4)
S17_32.S17_N: ChassisTimingInterface1 (P4.11), FPGA_ARTIX7 (U16.G3)
S17_32.S17_P: ChassisTimingInterface1 (P4.9), FPGA_ARTIX7 (U16.H3)
S17_32.S18_N: ChassisTimingInterface1 (P4.13), FPGA_ARTIX7 (U16.E3)
S17_32.S18_P: ChassisTimingInterface1 (P4.15), FPGA_ARTIX7 (U16.F3)
S17_32.S19_N: ChassisTimingInterface1 (P4.19), FPGA_ARTIX7 (U16.G2)
S17_32.S19_P: ChassisTimingInterface1 (P4.17), FPGA_ARTIX7 (U16.H2)
S17_32.S20_N: ChassisTimingInterface1 (P4.21), FPGA_ARTIX7 (U16.H5)
S17_32.S20_P: ChassisTimingInterface1 (P4.23), FPGA_ARTIX7 (U16.J5)
S17_32.S21_N: ChassisTimingInterface1 (P4.27), FPGA_ARTIX7 (U16.L4)
S17_32.S21_P: ChassisTimingInterface1 (P4.25), FPGA_ARTIX7 (U16.L5)
S17_32.S22_N: ChassisTimingInterface1 (P4.29), FPGA_ARTIX7 (U16.N3)
S17_32.S22_P: ChassisTimingInterface1 (P4.31), FPGA_ARTIX7 (U16.N4)
S17_32.S23_N: ChassisTimingInterface1 (P4.35), FPGA_ARTIX7 (U16.M2)
S17_32.S23_P: ChassisTimingInterface1 (P4.33), FPGA_ARTIX7 (U16.M3)
S17_32.S24_N: ChassisTimingInterface1 (P4.37), FPGA_ARTIX7 (U16.K3)
S17_32.S24_P: ChassisTimingInterface1 (P4.39), FPGA_ARTIX7 (U16.L3)
S17_32.S25_N: ChassisTimingInterface1 (P4.43), FPGA_ARTIX7 (U16.U5)
S17_32.S25_P: ChassisTimingInterface1 (P4.41), FPGA_ARTIX7 (U16.T5)
S17_32.S26_N: ChassisTimingInterface1 (P4.45), FPGA_ARTIX7 (U16.N2)
S17_32.S26_P: ChassisTimingInterface1 (P4.47), FPGA_ARTIX7 (U16.P2)
S17_32.S27_N: ChassisTimingInterface1 (P4.51), FPGA_ARTIX7 (U16.V3)
S17_32.S27_P: ChassisTimingInterface1 (P4.49), FPGA_ARTIX7 (U16.U3)
S17_32.S28_N: ChassisTimingInterface1 (P4.53), FPGA_ARTIX7 (U16.P4)
S17_32.S28_P: ChassisTimingInterface1 (P4.55), FPGA_ARTIX7 (U16.P5)
S17_32.S29_N: ChassisTimingInterface1 (P4.59), FPGA_ARTIX7 (U16.V5)
S17_32.S29_P: ChassisTimingInterface1 (P4.57), FPGA_ARTIX7 (U16.U6)
S17_32.S30_N: ChassisTimingInterface1 (P4.61), FPGA_ARTIX7 (U16.T6)
S17_32.S30_P: ChassisTimingInterface1 (P4.63), FPGA_ARTIX7 (U16.R6)
S17_32.S31_N: ChassisTimingInterface1 (P4.67), FPGA_ARTIX7 (U16.Y2)
S17_32.S31_P: ChassisTimingInterface1 (P4.65), FPGA_ARTIX7 (U16.W2)
S17_32.S32_N: ChassisTimingInterface1 (P4.69), FPGA_ARTIX7 (U16.AA4)
S17_32.S32_P: ChassisTimingInterface1 (P4.71), FPGA_ARTIX7 (U16.Y4)
S33_48.S33_N: ChassisTimingInterface1 (P5.11), FPGA_ARTIX7 (U16.F20)
S33_48.S33_P: ChassisTimingInterface1 (P5.9), FPGA_ARTIX7 (U16.F19)
S33_48.S34_N: ChassisTimingInterface1 (P5.13), FPGA_ARTIX7 (U16.D22)
S33_48.S34_P: ChassisTimingInterface1 (P5.15), FPGA_ARTIX7 (U16.E22)
S33_48.S35_N: ChassisTimingInterface1 (P5.19), FPGA_ARTIX7 (U16.G22)
S33_48.S35_P: ChassisTimingInterface1 (P5.17), FPGA_ARTIX7 (U16.G21)
S33_48.S36_N: ChassisTimingInterface1 (P5.21), FPGA_ARTIX7 (U16.H22)
S33_48.S36_P: ChassisTimingInterface1 (P5.23), FPGA_ARTIX7 (U16.J22)
S33_48.S37_N: ChassisTimingInterface1 (P5.27), FPGA_ARTIX7 (U16.E18)
S33_48.S37_P: ChassisTimingInterface1 (P5.25), FPGA_ARTIX7 (U16.F18)
S33_48.S38_N: ChassisTimingInterface1 (P5.29), FPGA_ARTIX7 (U16.G20)
S33_48.S38_P: ChassisTimingInterface1 (P5.31), FPGA_ARTIX7 (U16.H20)
S33_48.S39_N: ChassisTimingInterface1 (P5.35), FPGA_ARTIX7 (U16.J17)
S33_48.S39_P: ChassisTimingInterface1 (P5.33), FPGA_ARTIX7 (U16.K17)
S33_48.S40_N: ChassisTimingInterface1 (P5.37), FPGA_ARTIX7 (U16.C17)
S33_48.S40_P: ChassisTimingInterface1 (P5.39), FPGA_ARTIX7 (U16.D17)
S33_48.S41_N: ChassisTimingInterface1 (P5.43), FPGA_ARTIX7 (U16.K19)
S33_48.S41_P: ChassisTimingInterface1 (P5.41), FPGA_ARTIX7 (U16.K18)
S33_48.S42_N: ChassisTimingInterface1 (P5.45), FPGA_ARTIX7 (U16.K16)
S33_48.S42_P: ChassisTimingInterface1 (P5.47), FPGA_ARTIX7 (U16.L16)
S33_48.S43_N: ChassisTimingInterface1 (P5.51), FPGA_ARTIX7 (U16.K22)
S33_48.S43_P: ChassisTimingInterface1 (P5.49), FPGA_ARTIX7 (U16.K21)
S33_48.S44_N: ChassisTimingInterface1 (P5.53), FPGA_ARTIX7 (U16.L21)
S33_48.S44_P: ChassisTimingInterface1 (P5.55), FPGA_ARTIX7 (U16.M21)
S33_48.S45_N: ChassisTimingInterface1 (P5.59), FPGA_ARTIX7 (U16.R19)
S33_48.S45_P: ChassisTimingInterface1 (P5.57), FPGA_ARTIX7 (U16.P19)
S33_48.S46_N: ChassisTimingInterface1 (P5.61), FPGA_ARTIX7 (U16.M22)
S33_48.S46_P: ChassisTimingInterface1 (P5.63), FPGA_ARTIX7 (U16.N22)
S33_48.S47_N: ChassisTimingInterface1 (P5.67), FPGA_ARTIX7 (U16.U18)
S33_48.S47_P: ChassisTimingInterface1 (P5.65), FPGA_ARTIX7 (U16.U17)
S33_48.S48_N: ChassisTimingInterface1 (P5.69), FPGA_ARTIX7 (U16.H19)
S33_48.S48_P: ChassisTimingInterface1 (P5.71), FPGA_ARTIX7 (U16.J19)
S49_64.S49_N: ChassisTimingInterface1 (P5.12), FPGA_ARTIX7 (U16.D19)
S49_64.S49_P: ChassisTimingInterface1 (P5.10), FPGA_ARTIX7 (U16.E19)
S49_64.S50_N: ChassisTimingInterface1 (P5.14), FPGA_ARTIX7 (U16.F14)
S49_64.S50_P: ChassisTimingInterface1 (P5.16), FPGA_ARTIX7 (U16.F13)
S49_64.S51_N: ChassisTimingInterface1 (P5.20), FPGA_ARTIX7 (U16.G16)
S49_64.S51_P: ChassisTimingInterface1 (P5.18), FPGA_ARTIX7 (U16.G15)
S49_64.S52_N: ChassisTimingInterface1 (P5.22), FPGA_ARTIX7 (U16.H14)
S49_64.S52_P: ChassisTimingInterface1 (P5.24), FPGA_ARTIX7 (U16.J14)
S49_64.S53_N: ChassisTimingInterface1 (P5.28), FPGA_ARTIX7 (U16.G18)
S49_64.S53_P: ChassisTimingInterface1 (P5.26), FPGA_ARTIX7 (U16.G17)
S49_64.S54_N: ChassisTimingInterface1 (P5.30), FPGA_ARTIX7 (U16.H18)
S49_64.S54_P: ChassisTimingInterface1 (P5.32), FPGA_ARTIX7 (U16.H17)
S49_64.S55_N: ChassisTimingInterface1 (P5.36), FPGA_ARTIX7 (U16.K14)
S49_64.S55_P: ChassisTimingInterface1 (P5.34), FPGA_ARTIX7 (U16.K13)
S49_64.S56_N: ChassisTimingInterface1 (P5.38), FPGA_ARTIX7 (U16.J21)
S49_64.S56_P: ChassisTimingInterface1 (P5.40), FPGA_ARTIX7 (U16.J20)
S49_64.S57_N: ChassisTimingInterface1 (P5.44), FPGA_ARTIX7 (U16.L20)
S49_64.S57_P: ChassisTimingInterface1 (P5.42), FPGA_ARTIX7 (U16.L19)
S49_64.S58_N: ChassisTimingInterface1 (P5.46), FPGA_ARTIX7 (U16.E17)
S49_64.S58_P: ChassisTimingInterface1 (P5.48), FPGA_ARTIX7 (U16.F16)
S49_64.S59_N: ChassisTimingInterface1 (P5.52), FPGA_ARTIX7 (U16.M16)
S49_64.S59_P: ChassisTimingInterface1 (P5.50), FPGA_ARTIX7 (U16.M15)
S49_64.S60_N: ChassisTimingInterface1 (P5.54), FPGA_ARTIX7 (U16.M20)
S49_64.S60_P: ChassisTimingInterface1 (P5.56), FPGA_ARTIX7 (U16.N20)
S49_64.S61_N: ChassisTimingInterface1 (P5.60), FPGA_ARTIX7 (U16.P17)
S49_64.S61_P: ChassisTimingInterface1 (P5.58), FPGA_ARTIX7 (U16.N17)
S49_64.S62_N: ChassisTimingInterface1 (P5.62), FPGA_ARTIX7 (U16.T18)
S49_64.S62_P: ChassisTimingInterface1 (P5.64), FPGA_ARTIX7 (U16.R18)
S49_64.S63_N: ChassisTimingInterface1 (P5.68), FPGA_ARTIX7 (U16.U21)
S49_64.S63_P: ChassisTimingInterface1 (P5.66), FPGA_ARTIX7 (U16.T21)
S49_64.S64_N: ChassisTimingInterface1 (P5.70), FPGA_ARTIX7 (U16.V19)
S49_64.S64_P: ChassisTimingInterface1 (P5.72), FPGA_ARTIX7 (U16.V18)
SENSE.SENS_10_P: ChassisTimingInterface4 (C69.1 L4.2 R77.2 R96.1), ChassisTimingInterface_XADC (U5.3)
SENSE.SENS_18_P: ChassisTimingInterface4 (C46.2 L3.2 R48.1 R68.2), ChassisTimingInterface_XADC (U6.3)
SENSE.SENS_25_P: ChassisTimingInterface4 (C70.2 L5.2 R78.2 R97.1), ChassisTimingInterface_XADC (U8.3)
SENSE.SENS_33_P: ChassisTimingInterface4 (C45.2 L2.2 R49.1 R67.2), ChassisTimingInterface_XADC (U1.3)
SENSE.SENS_120b_P: ChassisTimingInterfacePCIE_HL (D2.2 R143.1), ChassisTimingInterface_XADC (R140.1)
SENSE.SENS_120x_P: ChassisTimingInterface4 (C74.1 D1.2 R99.1), ChassisTimingInterface_XADC (R46.2)
SFPIN.LEDIN: FPGA_ARTIX7 (U16.V17), ChassisTimingInterface_SFP (Q5.1)
SFPIN.LOS: FPGA_ARTIX7 (U16.W17), ChassisTimingInterface_SFP (J2.8 R114.1)
SFPIN.SYNCIN_N: FPGA_ARTIX7 (U16.R17), ChassisTimingInterface_SFP (U32.7)
SFPIN.SYNCIN_P: FPGA_ARTIX7 (U16.P16), ChassisTimingInterface_SFP (U32.6)
SFPIN.SYNCOUT_N: FPGA_ARTIX7 (U16.W22), ChassisTimingInterface_SFP (U33.2)
SFPIN.SYNCOUT_P: FPGA_ARTIX7 (U16.W21), ChassisTimingInterface_SFP (U33.3)
SQSPI.EMCLK_EN: ChassisTimingInterface3 (R38.2 Y1.1), FPGA_ARTIX7 (U16.U7)
SQSPI.PUDC_B: ChassisTimingInterface3 (R28.1 R29.1), FPGA_ARTIX7 (U16.U22)
SQSPI.QSPI_CS: ChassisTimingInterface3 (R42.2 U18.7 U20.1), FPGA_ARTIX7 (U16.T19)
SQSPI.QSPI_DQ0: ChassisTimingInterface3 (R35.2), FPGA_ARTIX7 (U16.P22)
SQSPI.QSPI_DQ1: ChassisTimingInterface3 (R31.2), FPGA_ARTIX7 (U16.R22)
SQSPI.QSPI_DQ2: ChassisTimingInterface3 (R30.2), FPGA_ARTIX7 (U16.P21)
SQSPI.QSPI_DQ3: ChassisTimingInterface3 (R39.2), FPGA_ARTIX7 (U16.R21)
SQSPI.QSPI_EMCLK: ChassisTimingInterface3 (Y1.3), FPGA_ARTIX7 (U16.V22)
SW1: ChassisTimingInterface1 (S1.16), FPGA_ARTIX7 (U16.T20)
SW2: ChassisTimingInterface1 (S1.15), FPGA_ARTIX7 (U16.P20)
SW3: ChassisTimingInterface1 (S1.14), FPGA_ARTIX7 (U16.N19)
SW4: ChassisTimingInterface1 (S1.13), FPGA_ARTIX7 (U16.N18)
SW5: ChassisTimingInterface1 (S1.12), FPGA_ARTIX7 (U16.N15)
SW6: ChassisTimingInterface1 (S1.11), FPGA_ARTIX7 (U16.N14)
SW7: ChassisTimingInterface1 (S1.10), FPGA_ARTIX7 (U16.K2)
SW8: ChassisTimingInterface1 (S1.9), FPGA_ARTIX7 (U16.J2)
SW9: ChassisTimingInterface1 (P4.6), FPGA_ARTIX7 (U16.N13)
SW10: ChassisTimingInterface1 (P4.8), FPGA_ARTIX7 (U16.L6)
T1_11.T1_N: ChassisTimingInterface1 (J4.14), FPGA_ARTIX7 (U16.V20)
T1_11.T1_P: ChassisTimingInterface1 (J4.1), FPGA_ARTIX7 (U16.U20)
T1_11.T2_N: ChassisTimingInterface1 (J4.15), FPGA_ARTIX7 (U16.L18)
T1_11.T2_P: ChassisTimingInterface1 (J4.2), FPGA_ARTIX7 (U16.M18)
T1_11.T3_N: ChassisTimingInterface1 (J4.16), FPGA_ARTIX7 (U16.R16)
T1_11.T3_P: ChassisTimingInterface1 (J4.3), FPGA_ARTIX7 (U16.P15)
T1_11.T4_N: ChassisTimingInterface1 (J4.17), FPGA_ARTIX7 (U16.L15)
T1_11.T4_P: ChassisTimingInterface1 (J4.4), FPGA_ARTIX7 (U16.L14)
T1_11.T5_N: ChassisTimingInterface1 (J4.18), FPGA_ARTIX7 (U16.R14)
T1_11.T5_P: ChassisTimingInterface1 (J4.5), FPGA_ARTIX7 (U16.P14)
T1_11.T6_N: ChassisTimingInterface1 (J4.19), FPGA_ARTIX7 (U16.Y9)
T1_11.T6_P: ChassisTimingInterface1 (J4.6), FPGA_ARTIX7 (U16.W9)
T1_11.T7_N: ChassisTimingInterface1 (J4.20), FPGA_ARTIX7 (U16.AB8)
T1_11.T7_P: ChassisTimingInterface1 (J4.7), FPGA_ARTIX7 (U16.AA8)
T1_11.T8_N: ChassisTimingInterface1 (J4.21), FPGA_ARTIX7 (U16.V8)
T1_11.T8_P: ChassisTimingInterface1 (J4.8), FPGA_ARTIX7 (U16.V9)
T1_11.T9_N: ChassisTimingInterface1 (J4.22), FPGA_ARTIX7 (U16.Y7)
T1_11.T9_P: ChassisTimingInterface1 (J4.9), FPGA_ARTIX7 (U16.Y8)
T10_N: ChassisTimingInterface1 (J4.23), FPGA_ARTIX7 (U16.AB6)
T10_P: ChassisTimingInterface1 (J4.10), FPGA_ARTIX7 (U16.AB7)
T11_N: ChassisTimingInterface1 (J4.24), FPGA_ARTIX7 (U16.W7)
T11_P: ChassisTimingInterface1 (J4.11), FPGA_ARTIX7 (U16.V7)
XADC.XADC_REF_N: ChassisTimingInterface3 (U16.L9), ChassisTimingInterface_XADC (W2.2)
XADC.XADC_REF_P: ChassisTimingInterface3 (U16.M10), ChassisTimingInterface_XADC (C201.1 R194.2 R199.2 U40.2)
XADC.XADC_V_N: ChassisTimingInterface3 (U16.M9), ChassisTimingInterface_XADC (C22.2 C148.2 R23.2)
XADC.XADC_V_P: ChassisTimingInterface3 (U16.L10), ChassisTimingInterface_XADC (C22.1 C148.1 R24.2)
XMUX0: FPGA_ARTIX7 (U16.F21), ChassisTimingInterface_XADC (U15.13)
XMUX1: FPGA_ARTIX7 (U16.M17), ChassisTimingInterface_XADC (U15.12)
XMUX2: FPGA_ARTIX7 (U16.J16), ChassisTimingInterface_XADC (U15.11)
XMUX3: FPGA_ARTIX7 (U16.F15), ChassisTimingInterface_XADC (U15.10)
XOCTRL_N: ChassisTimingInterface1 (J4.25), ChassisTimingInterface6 (R185.2)
XOCTRL_P: ChassisTimingInterface1 (J4.12), ChassisTimingInterface6 (R184.2)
